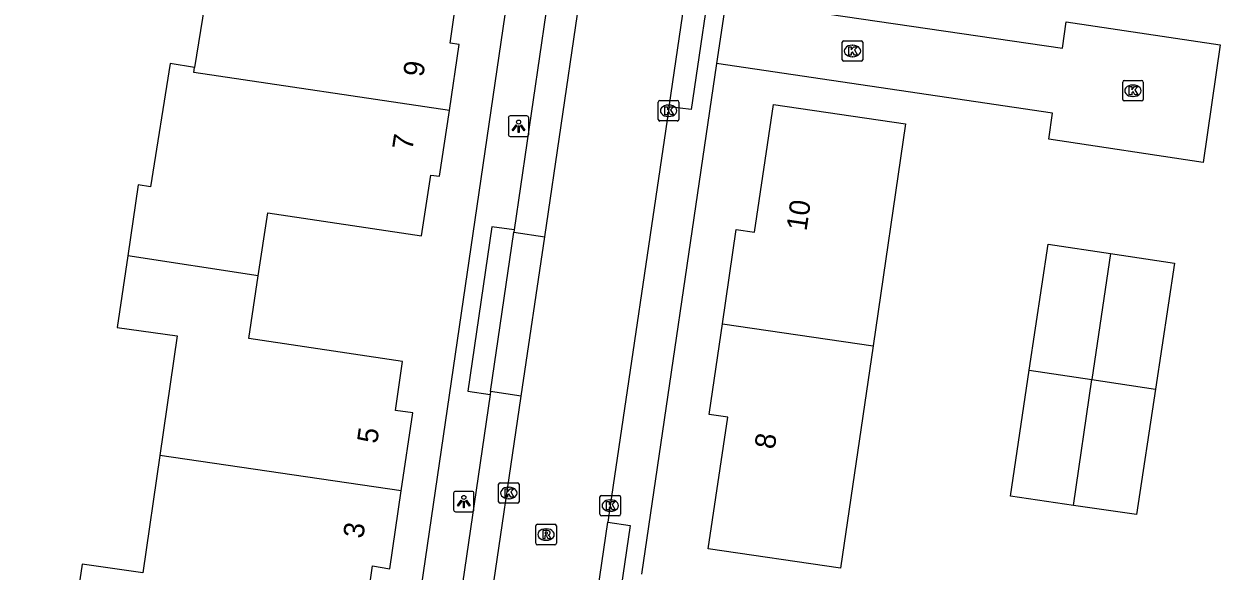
# Model space of a CAD drawing. Extents: x 164150 to 165261, y 382513 to 383432.
# Drawn here: x 164510.6 to 164569, y 382885.3 to 382912.1 of the extents above; entities that cross this region are included whole.
import ezdxf

# ---------------------------------------------------------------- set-up
doc = ezdxf.new("R2010")
doc.units = 0
for name, color, linetype in [('IMGEO_Kolk', 7, 'Continuous'), ('IMGEO_Lichtpunt', 7, 'Continuous'), ('IMGEO_Pand', 7, 'Continuous'), ('IMGEO_Pand_nummerreeks', 7, 'Continuous'), ('IMGEO_Rijbaan_lokaal_open', 7, 'Continuous'), ('IMGEO_Rioolput', 7, 'Continuous'), ('IMGEO_Voetpad_open', 7, 'Continuous')]:
    doc.layers.add(name, color=color, linetype=linetype)

msp = doc.modelspace()

# ---------------------------------------------------------------- linework, layer by layer
at = {"layer": 'IMGEO_Kolk'}
for p, q in [((164550.505, 382910.307), (164550.505, 382911.159)), ((164550.58, 382911.233), (164551.432, 382911.233)), ((164550.993, 382911.013), (164551.018, 382911.013)), ((164551.506, 382911.159), (164551.506, 382910.307)), ((164551.432, 382910.233), (164550.58, 382910.233)), ((164551.016, 382910.453), (164550.991, 382910.453)), ((164564.196, 382908.363), (164564.196, 382909.215)), ((164564.271, 382909.289), (164565.123, 382909.289)), ((164564.684, 382909.069), (164564.709, 382909.069)), ((164565.197, 382909.215), (164565.197, 382908.363)), ((164564.707, 382908.509), (164564.682, 382908.509)), ((164541.527, 382907.385), (164541.527, 382908.237)), ((164541.602, 382908.311), (164542.454, 382908.311)), ((164542.015, 382908.091), (164542.04, 382908.091)), ((164542.528, 382908.237), (164542.528, 382907.385)), ((164565.123, 382908.289), (164564.271, 382908.289)), ((164542.454, 382907.311), (164541.602, 382907.311)), ((164542.038, 382907.531), (164542.013, 382907.531)), ((164533.729, 382888.709), (164533.729, 382889.561)), ((164533.804, 382889.635), (164534.656, 382889.635)), ((164534.217, 382889.415), (164534.242, 382889.415)), ((164534.73, 382889.561), (164534.73, 382888.709)), ((164534.656, 382888.635), (164533.804, 382888.635)), ((164534.24, 382888.855), (164534.215, 382888.855)), ((164538.68, 382888.093), (164538.68, 382888.945)), ((164538.755, 382889.019), (164539.607, 382889.019)), ((164539.168, 382888.799), (164539.193, 382888.799)), ((164539.681, 382888.945), (164539.681, 382888.093)), ((164539.607, 382888.019), (164538.755, 382888.019)), ((164539.191, 382888.239), (164539.166, 382888.239))]:
    msp.add_line(p, q, dxfattribs=at)
for points in [[(164550.505, 382910.307), (164550.505, 382911.159)], [(164550.58, 382911.233), (164551.432, 382911.233)], [(164550.826, 382910.933), (164550.949, 382910.933), (164550.949, 382910.782), (164551.079, 382910.933), (164551.243, 382910.933), (164551.097, 382910.782), (164551.25, 382910.533), (164551.098, 382910.533), (164551.013, 382910.697), (164550.949, 382910.63), (164550.949, 382910.533), (164550.826, 382910.533), (164550.826, 382910.933)], [(164551.506, 382911.159), (164551.506, 382910.307)], [(164551.432, 382910.233), (164550.58, 382910.233)], [(164564.196, 382908.363), (164564.196, 382909.215)], [(164564.271, 382909.289), (164565.123, 382909.289)], [(164564.517, 382908.989), (164564.64, 382908.989), (164564.64, 382908.838), (164564.77, 382908.989), (164564.934, 382908.989), (164564.788, 382908.838), (164564.941, 382908.589), (164564.789, 382908.589), (164564.704, 382908.753), (164564.64, 382908.686), (164564.64, 382908.589), (164564.517, 382908.589), (164564.517, 382908.989)], [(164565.197, 382909.215), (164565.197, 382908.363)], [(164541.527, 382907.385), (164541.527, 382908.237)], [(164541.602, 382908.311), (164542.454, 382908.311)], [(164541.848, 382908.011), (164541.971, 382908.011), (164541.971, 382907.86), (164542.101, 382908.011), (164542.265, 382908.011), (164542.119, 382907.86), (164542.272, 382907.611), (164542.12, 382907.611), (164542.035, 382907.775), (164541.971, 382907.708), (164541.971, 382907.611), (164541.848, 382907.611), (164541.848, 382908.011)], [(164542.528, 382908.237), (164542.528, 382907.385)], [(164565.123, 382908.289), (164564.271, 382908.289)], [(164542.454, 382907.311), (164541.602, 382907.311)], [(164533.729, 382888.709), (164533.729, 382889.561)], [(164533.804, 382889.635), (164534.656, 382889.635)], [(164534.05, 382889.335), (164534.173, 382889.335), (164534.173, 382889.184), (164534.303, 382889.335), (164534.467, 382889.335), (164534.321, 382889.184), (164534.474, 382888.935), (164534.322, 382888.935), (164534.237, 382889.099), (164534.173, 382889.032), (164534.173, 382888.935), (164534.05, 382888.935), (164534.05, 382889.335)], [(164534.73, 382889.561), (164534.73, 382888.709)], [(164534.656, 382888.635), (164533.804, 382888.635)], [(164538.68, 382888.093), (164538.68, 382888.945)], [(164538.755, 382889.019), (164539.607, 382889.019)], [(164539.001, 382888.719), (164539.124, 382888.719), (164539.124, 382888.568), (164539.254, 382888.719), (164539.418, 382888.719), (164539.272, 382888.568), (164539.425, 382888.319), (164539.273, 382888.319), (164539.188, 382888.483), (164539.124, 382888.416), (164539.124, 382888.319), (164539.001, 382888.319), (164539.001, 382888.719)], [(164539.681, 382888.945), (164539.681, 382888.093)], [(164539.607, 382888.019), (164538.755, 382888.019)]]:
    msp.add_lwpolyline(points, dxfattribs=at)
for centre, start, end in [((164550.582, 382911.157), 91.55205, 178.44795), ((164550.582, 382911.157), 91.55205, 178.44795), ((164551.43, 382911.157), 1.55205, 88.44795), ((164551.43, 382911.157), 1.55205, 88.44795), ((164550.582, 382910.309), 181.55205, 268.44795), ((164550.582, 382910.309), 181.55205, 268.44795), ((164551.43, 382910.309), 271.55205, 358.44795), ((164551.43, 382910.309), 271.55205, 358.44795), ((164564.273, 382909.213), 91.55205, 178.44795), ((164564.273, 382909.213), 91.55205, 178.44795), ((164565.121, 382909.213), 1.55205, 88.44795), ((164565.121, 382909.213), 1.55205, 88.44795), ((164541.604, 382908.235), 91.55205, 178.44795), ((164541.604, 382908.235), 91.55205, 178.44795), ((164542.452, 382908.235), 1.55205, 88.44795), ((164542.452, 382908.235), 1.55205, 88.44795), ((164564.273, 382908.365), 181.55205, 268.44795), ((164564.273, 382908.365), 181.55205, 268.44795), ((164565.121, 382908.365), 271.55205, 358.44795), ((164565.121, 382908.365), 271.55205, 358.44795), ((164541.604, 382907.387), 181.55205, 268.44795), ((164541.604, 382907.387), 181.55205, 268.44795), ((164542.452, 382907.387), 271.55205, 358.44795), ((164542.452, 382907.387), 271.55205, 358.44795), ((164533.806, 382889.559), 91.55205, 178.44795), ((164533.806, 382889.559), 91.55205, 178.44795), ((164534.654, 382889.559), 1.55205, 88.44795), ((164534.654, 382889.559), 1.55205, 88.44795), ((164533.806, 382888.711), 181.55205, 268.44795), ((164533.806, 382888.711), 181.55205, 268.44795), ((164534.654, 382888.711), 271.55205, 358.44795), ((164534.654, 382888.711), 271.55205, 358.44795), ((164538.757, 382888.943), 91.55205, 178.44795), ((164538.757, 382888.943), 91.55205, 178.44795), ((164539.605, 382888.943), 1.55205, 88.44795), ((164539.605, 382888.943), 1.55205, 88.44795), ((164538.757, 382888.095), 181.55205, 268.44795), ((164538.757, 382888.095), 181.55205, 268.44795), ((164539.605, 382888.095), 271.55205, 358.44795), ((164539.605, 382888.095), 271.55205, 358.44795)]:
    msp.add_arc(centre, 0.0765, start, end, dxfattribs=at)
for centre, major_axis, ratio, start_param, end_param in [((164550.992, 382910.733), (-0.387, 0.002), 0.722429, 4.712389, 7.853982), ((164551.017, 382910.733), (-0.39, 0.002), 0.717154, 1.570796, 4.712389), ((164564.683, 382908.789), (-0.387, 0.002), 0.722429, 4.712389, 7.853982), ((164564.708, 382908.789), (-0.39, 0.002), 0.717154, 1.570796, 4.712389), ((164542.014, 382907.811), (-0.387, 0.002), 0.722429, 4.712389, 7.853982), ((164542.039, 382907.811), (-0.39, 0.002), 0.717154, 1.570796, 4.712389), ((164534.216, 382889.135), (-0.387, 0.002), 0.722429, 4.712389, 7.853982), ((164534.241, 382889.135), (-0.39, 0.002), 0.717154, 1.570796, 4.712389), ((164539.167, 382888.519), (-0.387, 0.002), 0.722429, 4.712389, 7.853982), ((164539.192, 382888.519), (-0.39, 0.002), 0.717154, 1.570796, 4.712389)]:
    msp.add_ellipse(centre, major_axis=major_axis, ratio=ratio, start_param=start_param, end_param=end_param, dxfattribs=at)
at = {"layer": 'IMGEO_Lichtpunt'}
for p, q in [((164534.206, 382907.461), (164534.206, 382906.654)), ((164534.206, 382907.461), (164534.206, 382906.654)), ((164535.108, 382907.556), (164534.3, 382907.556)), ((164535.108, 382907.556), (164534.3, 382907.556)), ((164535.202, 382906.654), (164535.202, 382907.461)), ((164535.202, 382906.654), (164535.202, 382907.461)), ((164534.3, 382906.56), (164535.108, 382906.56)), ((164534.3, 382906.56), (164535.108, 382906.56)), ((164531.533, 382889.118), (164531.533, 382888.311)), ((164531.533, 382889.118), (164531.533, 382888.311)), ((164532.435, 382889.213), (164531.627, 382889.213)), ((164532.435, 382889.213), (164531.627, 382889.213)), ((164532.529, 382888.311), (164532.529, 382889.118)), ((164532.529, 382888.311), (164532.529, 382889.118)), ((164531.627, 382888.217), (164532.435, 382888.217)), ((164531.627, 382888.217), (164532.435, 382888.217))]:
    msp.add_line(p, q, dxfattribs=at)
for points in [[(164534.58, 382907.125), (164534.619, 382907.097), (164534.431, 382906.835), (164534.393, 382906.862), (164534.58, 382907.125)], [(164534.682, 382907.077), (164534.729, 382907.077), (164534.729, 382906.755), (164534.682, 382906.755), (164534.682, 382907.077)], [(164534.792, 382907.097), (164534.83, 382907.124), (164535.017, 382906.862), (164534.978, 382906.834), (164534.792, 382907.097)], [(164531.907, 382888.782), (164531.946, 382888.754), (164531.758, 382888.492), (164531.72, 382888.519), (164531.907, 382888.782)], [(164532.009, 382888.734), (164532.056, 382888.734), (164532.056, 382888.412), (164532.009, 382888.412), (164532.009, 382888.734)], [(164532.119, 382888.754), (164532.157, 382888.781), (164532.344, 382888.519), (164532.305, 382888.491), (164532.119, 382888.754)]]:
    msp.add_lwpolyline(points, dxfattribs=at)
for centre in [(164534.705, 382907.259), (164532.032, 382888.916)]:
    msp.add_circle(centre, 0.0994, dxfattribs=at)
for centre, start, end in [((164534.3, 382907.461), 90, 180), ((164534.3, 382907.461), 90, 180), ((164535.108, 382907.461), 0, 90), ((164535.108, 382907.461), 0, 90), ((164534.3, 382906.654), 180, 270), ((164534.3, 382906.654), 180, 270), ((164535.108, 382906.654), 270, 0), ((164535.108, 382906.654), 270, 360), ((164531.627, 382889.118), 90, 180), ((164531.627, 382889.118), 90, 180), ((164532.435, 382889.118), 0, 90), ((164532.435, 382889.118), 0, 90), ((164531.627, 382888.311), 180, 270), ((164531.627, 382888.311), 180, 270), ((164532.435, 382888.311), 270, 0), ((164532.435, 382888.311), 270, 360)]:
    msp.add_arc(centre, 0.0946, start, end, dxfattribs=at)
at = {"layer": 'IMGEO_Pand'}
for points in [[(164518.367, 382919.245), (164517.849, 382915.767), (164519.78, 382915.457), (164518.893, 382909.931)], [(164531.329, 382907.829), (164531.805, 382911.044), (164531.359, 382911.106), (164531.797, 382914.074), (164524.258, 382915.194), (164524.728, 382918.276)], [(164518.893, 382909.931), (164517.701, 382910.122), (164516.733, 382904.093), (164516.141, 382904.189), (164515.63, 382900.722)], [(164531.329, 382907.829), (164518.852, 382909.677), (164518.893, 382909.931)], [(164522.001, 382899.752), (164522.469, 382902.828), (164529.967, 382901.7), (164530.422, 382904.67), (164530.852, 382904.613), (164531.329, 382907.829)], [(164544.653, 382897.396), (164545.331, 382902.007), (164546.228, 382901.875), (164547.146, 382908.121), (164553.602, 382907.172), (164552.01, 382896.317)], [(164559.636, 382895.134), (164560.557, 382901.286), (164563.604, 382900.831)], [(164563.604, 382900.831), (164562.698, 382894.676)], [(164563.604, 382900.831), (164566.727, 382900.365), (164565.798, 382894.211)], [(164515.63, 382900.722), (164515.115, 382897.228), (164518.037, 382896.807), (164517.196, 382890.97)], [(164522.001, 382899.752), (164515.63, 382900.722)], [(164528.982, 382889.238), (164529.541, 382893.043), (164528.691, 382893.168), (164529.042, 382895.565), (164521.532, 382896.676), (164522.001, 382899.752)], [(164552.01, 382896.317), (164550.418, 382885.462), (164543.969, 382886.409), (164544.914, 382892.835), (164544.003, 382892.969), (164544.02, 382893.085), (164544.653, 382897.396)], [(164544.653, 382897.396), (164552.01, 382896.317)], [(164561.794, 382888.529), (164558.715, 382888.982), (164559.636, 382895.134)], [(164559.636, 382895.134), (164562.698, 382894.676)], [(164561.794, 382888.529), (164562.698, 382894.676)], [(164562.698, 382894.676), (164565.798, 382894.211)], [(164565.798, 382894.211), (164564.872, 382888.076), (164561.794, 382888.529)], [(164517.196, 382890.97), (164516.368, 382885.227), (164513.394, 382885.655), (164512.877, 382882.156)], [(164528.982, 382889.238), (164517.196, 382890.97)], [(164519.273, 382881.212), (164519.728, 382884.295), (164527.229, 382883.186), (164527.578, 382885.569), (164528.423, 382885.433), (164528.982, 382889.238)]]:
    msp.add_lwpolyline(points, dxfattribs=at)
at = {"layer": 'IMGEO_Rijbaan_lokaal_open'}
for points in [[(164542.057, 382908.011), (164543.215, 382915.889)], [(164544.836, 382913.278), (164561.257, 382910.871), (164561.444, 382912.157), (164568.951, 382911.025), (164568.121, 382905.277), (164560.589, 382906.422), (164560.768, 382907.691), (164544.373, 382910.128)], [(164544.836, 382913.278), (164544.373, 382910.128)], [(164535.985, 382901.658), (164537.586, 382912.536)], [(164542.057, 382908.011), (164542.028, 382907.811), (164539.181, 382888.519), (164539.063, 382887.71)], [(164534.839, 382893.869), (164535.985, 382901.658)], [(164533.255, 382883.11), (164534.839, 382893.869)], [(164537.91, 382879.804), (164539.063, 382887.71)]]:
    msp.add_lwpolyline(points, dxfattribs=at)
at = {"layer": 'IMGEO_Rioolput'}
for p, q in [((164535.548, 382886.677), (164535.548, 382887.529)), ((164535.623, 382887.603), (164536.475, 382887.603)), ((164536.036, 382887.383), (164536.061, 382887.383)), ((164536.549, 382887.529), (164536.549, 382886.677)), ((164536.059, 382886.823), (164536.034, 382886.823)), ((164536.475, 382886.603), (164535.623, 382886.603))]:
    msp.add_line(p, q, dxfattribs=at)
for points in [[(164535.548, 382886.677), (164535.548, 382887.529)], [(164535.623, 382887.603), (164536.475, 382887.603)], [(164536.549, 382887.529), (164536.549, 382886.677)], [(164536.137, 382887.301), (164535.885, 382887.303), (164535.885, 382886.903)], [(164535.885, 382886.903), (164536.009, 382886.903), (164536.009, 382887.065), (164536.02, 382887.065)], [(164536.063, 382887.222), (164536.009, 382887.222), (164536.009, 382887.141)], [(164536.009, 382887.141), (164536.061, 382887.141)], [(164536.067, 382887.036), (164536.138, 382886.903), (164536.278, 382886.903), (164536.213, 382887.029)], [(164536.475, 382886.603), (164535.623, 382886.603)]]:
    msp.add_lwpolyline(points, dxfattribs=at)
for centre, radius, start, end in [((164535.625, 382887.527), 0.0765, 91.55205, 178.44795), ((164535.625, 382887.527), 0.0765, 91.55205, 178.44795), ((164536.473, 382887.527), 0.0765, 1.55205, 88.44795), ((164536.473, 382887.527), 0.0765, 1.55205, 88.44795), ((164536.019, 382887.012), 0.0533, 26.02933, 88.69889), ((164536.045, 382887.33), 0.19, 274.7715, 282.96867), ((164536.069, 382887.126), 0.0964, 77.00612, 93.18647), ((164536.083, 382887.183), 0.0378, 276.66336, 79.67722), ((164536.136, 382887.191), 0.109, 350.36119, 89.41601), ((164536.134, 382887.191), 0.112, 277.58423, 350.98172), ((164536.118, 382886.976), 0.108, 29.51342, 73.79051), ((164535.625, 382886.679), 0.0765, 181.55205, 268.44795), ((164535.625, 382886.679), 0.0765, 181.55205, 268.44795), ((164536.473, 382886.679), 0.0765, 271.55205, 358.44795), ((164536.473, 382886.679), 0.0765, 271.55205, 358.44795)]:
    msp.add_arc(centre, radius, start, end, dxfattribs=at)
for centre, major_axis, ratio, start_param, end_param in [((164536.035, 382887.103), (-0.387, 0.002), 0.722429, 4.712389, 7.853982), ((164536.06, 382887.103), (-0.39, 0.002), 0.717154, 1.570796, 4.712389)]:
    msp.add_ellipse(centre, major_axis=major_axis, ratio=ratio, start_param=start_param, end_param=end_param, dxfattribs=at)
at = {"layer": 'IMGEO_Voetpad_open'}
for points in [[(164527.73, 382869.322), (164536.67, 382930.425), (164544.133, 382980.726), (164542.913, 382982.243), (164519.298, 382985.737), (164495.986, 382989.176)], [(164543.215, 382915.889), (164544.281, 382915.734), (164543.135, 382907.871), (164542.057, 382908.011)], [(164536.041, 382912.575), (164534.494, 382901.996)], [(164544.373, 382910.128), (164540.7, 382885.173)], [(164534.494, 382901.996), (164533.408, 382902.146), (164532.221, 382894.112), (164533.317, 382893.95)], [(164534.494, 382901.996), (164534.476, 382901.877)], [(164533.337, 382894.09), (164534.476, 382901.877)], [(164534.476, 382901.877), (164535.985, 382901.658)], [(164533.317, 382893.95), (164531.771, 382883.381)], [(164533.337, 382894.09), (164533.317, 382893.95)], [(164534.839, 382893.869), (164533.337, 382894.09)], [(164539.063, 382887.71), (164540.151, 382887.546), (164539.003, 382879.661), (164537.91, 382879.804)]]:
    msp.add_lwpolyline(points, dxfattribs=at)

# ---------------------------------------------------------------- texts
at = {"layer": 'IMGEO_Pand_nummerreeks'}
for s, rotation, p in [('9', 81.572, (164530.05, 382909.431)), ('7', 81.572, (164529.519, 382905.849)), ('10', 81.64076, (164548.759, 382901.903)), ('5', 81.64076, (164527.8, 382891.516)), ('8', 81.63503, (164547.206, 382891.242)), ('3', 81.64076, (164527.119, 382886.881))]:
    msp.add_text(s, height=1, rotation=rotation, dxfattribs=at).set_placement(p)

doc.saveas('drawing.dxf')
